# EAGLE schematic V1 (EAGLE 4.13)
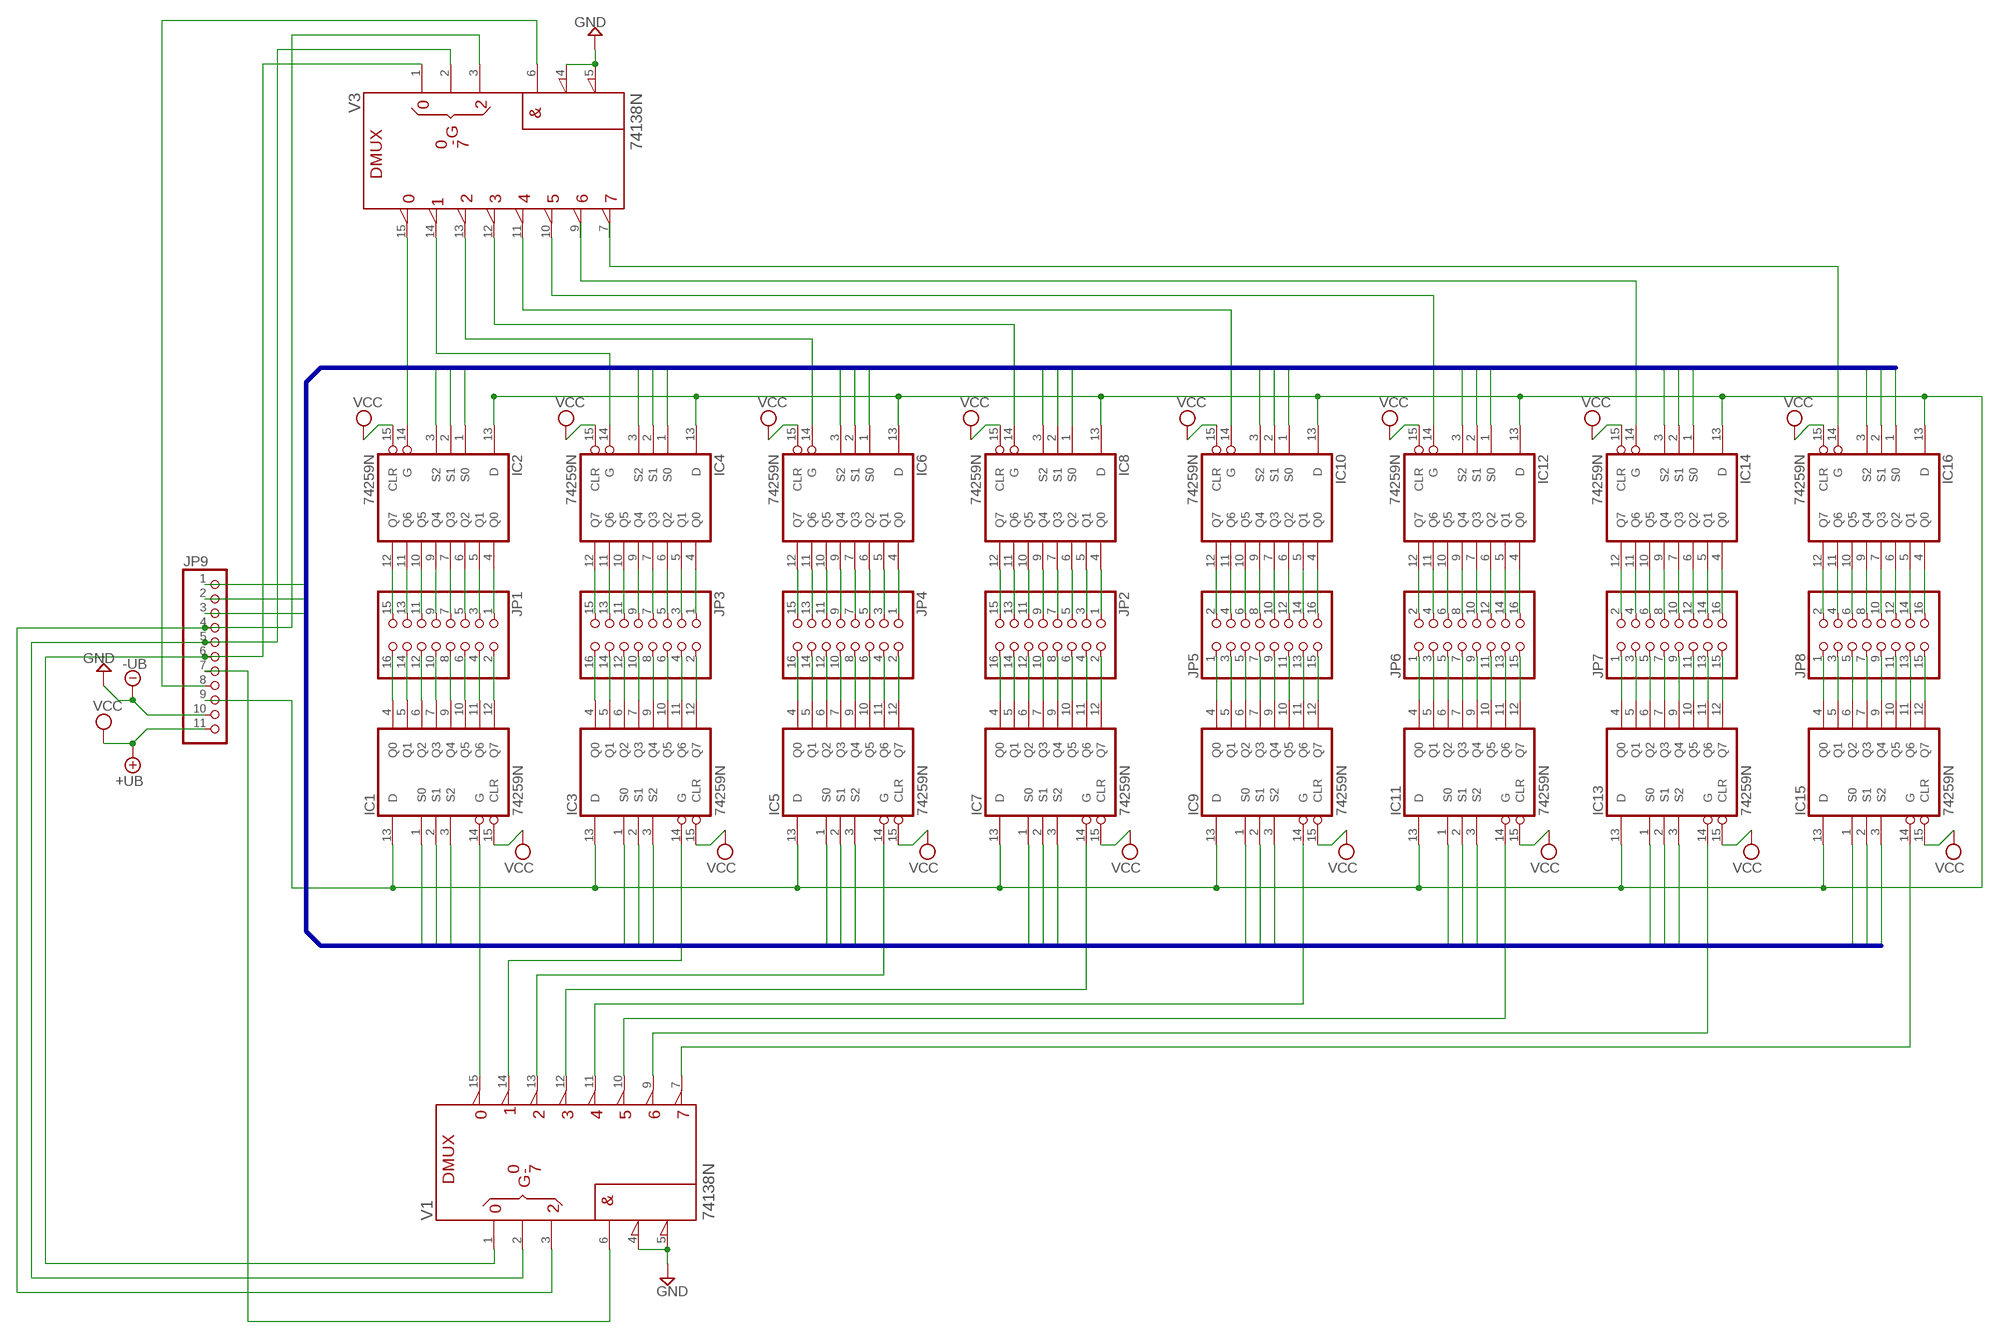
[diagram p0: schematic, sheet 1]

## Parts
IC1  74259N  [DIL16]
IC2  74259N  [DIL16]
IC3  74259N  [DIL16]
IC4  74259N  [DIL16]
IC5  74259N  [DIL16]
IC6  74259N  [DIL16]
IC7  74259N  [DIL16]
IC8  74259N  [DIL16]
IC9  74259N  [DIL16]
IC10  74259N  [DIL16]
IC11  74259N  [DIL16]
IC12  74259N  [DIL16]
IC13  74259N  [DIL16]
IC14  74259N  [DIL16]
IC15  74259N  [DIL16]
IC16  74259N  [DIL16]
JP1  PINHD-2X8  [2X08]
JP2  PINHD-2X8  [2X08]
JP3  PINHD-2X8  [2X08]
JP4  PINHD-2X8  [2X08]
JP5  PINHD-2X8  [2X08]
JP6  PINHD-2X8  [2X08]
JP7  PINHD-2X8  [2X08]
JP8  PINHD-2X8  [2X08]
JP9  PINHD-1X11  [1X11]
V1  74138N  [DIL16]
V3  74138N  [DIL16]

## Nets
B0: IC1.3(S2) IC2.3(S2) IC3.3(S2) IC4.3(S2) IC5.3(S2) IC6.3(S2) IC7.3(S2) IC8.3(S2) IC9.3(S2) IC10.3(S2) IC11.3(S2) IC12.3(S2) IC13.3(S2) IC14.3(S2) IC15.3(S2) IC16.3(S2) JP9.1
B1: IC1.2(S1) IC2.2(S1) IC3.2(S1) IC4.2(S1) IC5.2(S1) IC6.2(S1) IC7.2(S1) IC8.2(S1) IC9.2(S1) IC10.2(S1) IC11.2(S1) IC12.2(S1) IC13.2(S1) IC14.2(S1) IC15.2(S1) IC16.2(S1) JP9.2
B2: IC1.1(S0) IC2.1(S0) IC3.1(S0) IC4.1(S0) IC5.1(S0) IC6.1(S0) IC7.1(S0) IC8.1(S0) IC9.1(S0) IC10.1(S0) IC11.1(S0) IC12.1(S0) IC13.1(S0) IC14.1(S0) IC15.1(S0) IC16.1(S0) JP9.3
GND: JP9.10 V1.4(G\2A) V1.5(G\2B) V3.4(G\2A) V3.5(G\2B) ; supply symbol labelled -UB
MD1A0: IC1.4(Q0) JP1.16
MD1A1: IC1.5(Q1) JP1.14
MD1A2: IC1.6(Q2) JP1.12
MD1A3: IC1.7(Q3) JP1.10
MD1A4: IC1.9(Q4) JP1.8
MD1A5: IC1.10(Q5) JP1.6
MD1A6: IC1.11(Q6) JP1.4
MD1A7: IC1.12(Q7) JP1.2
MD1B0: IC9.4(Q0) JP5.1
MD1B1: IC9.5(Q1) JP5.3
MD1B2: IC9.6(Q2) JP5.5
MD1B3: IC9.7(Q3) JP5.7
MD1B4: IC9.9(Q4) JP5.9
MD1B5: IC9.10(Q5) JP5.11
MD1B6: IC9.11(Q6) JP5.13
MD1B7: IC9.12(Q7) JP5.15
MD2A0: IC2.4(Q0) JP1.1
MD2A1: IC2.5(Q1) JP1.3
MD2A2: IC2.6(Q2) JP1.5
MD2A3: IC2.7(Q3) JP1.7
MD2A4: IC2.9(Q4) JP1.9
MD2A5: IC2.10(Q5) JP1.11
MD2A6: IC2.11(Q6) JP1.13
MD2A7: IC2.12(Q7) JP1.15
MD2B0: IC10.4(Q0) JP5.16
MD2B1: IC10.5(Q1) JP5.14
MD2B2: IC10.6(Q2) JP5.12
MD2B3: IC10.7(Q3) JP5.10
MD2B4: IC10.9(Q4) JP5.8
MD2B5: IC10.10(Q5) JP5.6
MD2B6: IC10.11(Q6) JP5.4
MD2B7: IC10.12(Q7) JP5.2
MD3B0: IC11.4(Q0) JP6.1
MD3B1: IC11.5(Q1) JP6.3
MD3B2: IC11.6(Q2) JP6.5
MD3B3: IC11.7(Q3) JP6.7
MD3B4: IC11.9(Q4) JP6.9
MD3B5: IC11.10(Q5) JP6.11
MD3B6: IC11.11(Q6) JP6.13
MD3B7: IC11.12(Q7) JP6.15
MD4A0: IC4.4(Q0) JP3.1
MD4A1: IC4.5(Q1) JP3.3
MD4A2: IC4.6(Q2) JP3.5
MD4A3: IC4.7(Q3) JP3.7
MD4A4: IC4.9(Q4) JP3.9
MD4A5: IC4.10(Q5) JP3.11
MD4A6: IC4.11(Q6) JP3.13
MD4A7: IC4.12(Q7) JP3.15
MD4B0: IC12.4(Q0) JP6.16
MD4B1: IC12.5(Q1) JP6.14
MD4B2: IC12.6(Q2) JP6.12
MD4B3: IC12.7(Q3) JP6.10
MD4B4: IC12.9(Q4) JP6.8
MD4B5: IC12.10(Q5) JP6.6
MD4B6: IC12.11(Q6) JP6.4
MD4B7: IC12.12(Q7) JP6.2
MD5B0: IC13.4(Q0) JP7.1
MD5B1: IC13.5(Q1) JP7.3
MD5B2: IC13.6(Q2) JP7.5
MD5B3: IC13.7(Q3) JP7.7
MD5B4: IC13.9(Q4) JP7.9
MD5B5: IC13.10(Q5) JP7.11
MD5B6: IC13.11(Q6) JP7.13
MD5B7: IC13.12(Q7) JP7.15
MD6B0: IC14.4(Q0) JP7.16
MD6B1: IC14.5(Q1) JP7.14
MD6B2: IC14.6(Q2) JP7.12
MD6B3: IC14.7(Q3) JP7.10
MD6B4: IC14.9(Q4) JP7.8
MD6B5: IC14.10(Q5) JP7.6
MD6B6: IC14.11(Q6) JP7.4
MD6B7: IC14.12(Q7) JP7.2
MD7A0: IC7.4(Q0) JP2.16
MD7A1: IC7.5(Q1) JP2.14
MD7A2: IC7.6(Q2) JP2.12
MD7A3: IC7.7(Q3) JP2.10
MD7A4: IC7.9(Q4) JP2.8
MD7A5: IC7.10(Q5) JP2.6
MD7A6: IC7.11(Q6) JP2.4
MD7A7: IC7.12(Q7) JP2.2
MD7B0: IC15.4(Q0) JP8.1
MD7B1: IC15.5(Q1) JP8.3
MD7B2: IC15.6(Q2) JP8.5
MD7B3: IC15.7(Q3) JP8.7
MD7B4: IC15.9(Q4) JP8.9
MD7B5: IC15.10(Q5) JP8.11
MD7B6: IC15.11(Q6) JP8.13
MD7B7: IC15.12(Q7) JP8.15
MD8B0: IC16.4(Q0) JP8.16
MD8B1: IC16.5(Q1) JP8.14
MD8B2: IC16.6(Q2) JP8.12
MD8B3: IC16.7(Q3) JP8.10
MD8B4: IC16.9(Q4) JP8.8
MD8B5: IC16.10(Q5) JP8.6
MD8B6: IC16.11(Q6) JP8.4
MD8B7: IC16.12(Q7) JP8.2
N$1: IC3.4(Q0) JP3.16
N$2: IC3.5(Q1) JP3.14
N$3: IC3.6(Q2) JP3.12
N$4: IC3.7(Q3) JP3.10
N$5: IC3.9(Q4) JP3.8
N$6: IC3.10(Q5) JP3.6
N$7: IC3.11(Q6) JP3.4
N$8: IC3.12(Q7) JP3.2
N$9: IC6.12(Q7) JP4.15
N$10: IC6.11(Q6) JP4.13
N$11: IC6.10(Q5) JP4.11
N$12: IC6.9(Q4) JP4.9
N$13: IC6.7(Q3) JP4.7
N$14: IC6.6(Q2) JP4.5
N$15: IC6.5(Q1) JP4.3
N$16: IC6.4(Q0) JP4.1
N$17: IC5.4(Q0) JP4.16
N$18: IC5.5(Q1) JP4.14
N$19: IC5.6(Q2) JP4.12
N$20: IC5.7(Q3) JP4.10
N$21: IC5.9(Q4) JP4.8
N$22: IC5.10(Q5) JP4.6
N$23: IC5.11(Q6) JP4.4
N$24: IC5.12(Q7) JP4.2
N$25: IC8.12(Q7) JP2.15
N$26: IC8.11(Q6) JP2.13
N$27: IC8.10(Q5) JP2.11
N$28: IC8.9(Q4) JP2.9
N$29: IC8.7(Q3) JP2.7
N$30: IC8.6(Q2) JP2.5
N$31: IC8.5(Q1) JP2.3
N$32: IC8.4(Q0) JP2.1
N$33: IC2.14(G) V3.15(Y0)
N$34: IC1.13(D) IC2.13(D) IC3.13(D) IC4.13(D) IC5.13(D) IC6.13(D) IC7.13(D) IC8.13(D) IC9.13(D) IC10.13(D) IC11.13(D) IC12.13(D) IC13.13(D) IC14.13(D) IC15.13(D) IC16.13(D) JP9.9
N$35: IC4.14(G) V3.14(Y1)
N$36: IC6.14(G) V3.13(Y2)
N$37: IC8.14(G) V3.12(Y3)
N$38: IC10.14(G) V3.11(Y4)
N$39: IC12.14(G) V3.10(Y5)
N$40: IC14.14(G)
N$41: IC16.14(G)
N$42: IC1.14(G) V1.15(Y0)
N$43: IC3.14(G) V1.14(Y1)
N$44: IC5.14(G) V1.13(Y2)
N$45: IC7.14(G) V1.12(Y3)
N$46: IC9.14(G) V1.11(Y4)
N$47: IC11.14(G) V1.10(Y5)
N$48: IC13.14(G) V1.9(Y6)
N$49: IC15.14(G) V1.7(Y7)
N$50: JP9.8 V3.6(G1)
N$51: JP9.7 V1.6(G1)
N$53: JP9.6 V1.1(A) V3.1(A)
N$54: JP9.5 V1.2(B) V3.2(B)
N$55: JP9.4 V1.3(C) V3.3(C)
VCC: IC1.15(CLR) IC2.15(CLR) IC3.15(CLR) IC4.15(CLR) IC5.15(CLR) IC6.15(CLR) IC7.15(CLR) IC8.15(CLR) IC9.15(CLR) IC10.15(CLR) IC11.15(CLR) IC12.15(CLR) IC13.15(CLR) IC14.15(CLR) IC15.15(CLR) IC16.15(CLR) JP9.11 ; supply symbol labelled +UB
Unconnected: V3.7(Y7) V3.9(Y6)

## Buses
B[0..2]

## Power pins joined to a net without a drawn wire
+UB: V1.16(+UB) V3.16(+UB)
-UB: V1.8(-UB) V3.8(-UB)
GND: IC1.8(GND) IC2.8(GND) IC3.8(GND) IC4.8(GND) IC5.8(GND) IC6.8(GND) IC7.8(GND) IC8.8(GND) IC9.8(GND) IC10.8(GND) IC11.8(GND) IC12.8(GND) IC13.8(GND) IC14.8(GND) IC15.8(GND) IC16.8(GND)
VCC: IC1.16(VCC) IC2.16(VCC) IC3.16(VCC) IC4.16(VCC) IC5.16(VCC) IC6.16(VCC) IC7.16(VCC) IC8.16(VCC) IC9.16(VCC) IC10.16(VCC) IC11.16(VCC) IC12.16(VCC) IC13.16(VCC) IC14.16(VCC) IC15.16(VCC) IC16.16(VCC)

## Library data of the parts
IC1-IC16 = 74xx-us:74*259: 8-bit addressable LATCH
JP1-JP8 = pinhead:PINHD-2X8: PIN HEADER
JP9 = pinhead:PINHD-1X11: PIN HEADER
V1 V3 = 74ttl-din:74*138: 3-line to 8-line DECODER/DEMULTIPLEXER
